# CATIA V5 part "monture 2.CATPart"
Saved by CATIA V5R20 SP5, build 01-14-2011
Part number: monture 2
Publications: "Face", "Face1", "Face2", "Face3"
Bounding box of the stored display mesh (mm): x -200 to 10, y -75 to 75, z -75 to 75
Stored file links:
  U:\IAO\Nouveau dossier\monture 2.CATPart
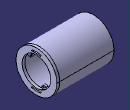
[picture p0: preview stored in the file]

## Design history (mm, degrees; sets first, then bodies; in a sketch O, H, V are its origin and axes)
Body1 (main body)
  Sketch1 on yz-plane, origin (0, 0, 0), H (0, 1, 0), V (0, 0, 1)
    circle A1 centre (0, 0) radius 75
    arc A2 centre (0, 0) radius 62.5 from (15.625, 60.5154) to (-15.625, 60.5154) ccw
    arc A3 centre (0, 0) radius 57.5 from (14.375, 55.6741) to (-14.375, 55.6741) ccw
    arc A4 centre (-15, 58.0948) radius 2.5 from (-15.625, 60.5154) to (-14.375, 55.6741) ccw
    point P1 (-15, 58.0948)
    arc A5 centre (15, 58.0948) radius 2.5 from (15.625, 60.5154) to (14.375, 55.6741) cw
    point P3 (15.625, 60.5154)
    point P4 (14.375, 55.6741)
    point P5 (-14.375, 55.6741)
    point P6 (-15.625, 60.5154)
    point P7 (-14.375, -55.6741)
    point P8 (-15.625, -60.5154)
    arc A6 centre (-15, -58.0948) radius 2.5 from (-15.625, -60.5154) to (-14.375, -55.6741) cw
    point P10 (14.375, -55.6741)
    point P11 (15.625, -60.5154)
    arc A7 centre (15, -58.0948) radius 2.5 from (15.625, -60.5154) to (14.375, -55.6741) ccw
    arc A8 centre (0, 0) radius 62.5 from (-15.625, -60.5154) to (15.625, -60.5154) ccw
    arc A9 centre (0, 0) radius 57.5 from (-14.375, -55.6741) to (14.375, -55.6741) ccw
    arc A10 centre (0, 0) radius 52.5 from (-38.2218, 35.9909) to (17.3744, -49.5417) ccw
    point P13 (-26, 40)
    construction line L1 through (0, -7.6191) direction (0, 1)
    construction line L2 through (0.6485, 0) direction (1, 0)
    arc A11 centre (-26, 40) radius 7.5 from (-32.0715, 35.597) to (-19.5113, 43.7612) ccw
    point P14 (0, 0)
    arc A12 centre (-16.0506, 45.7671) radius 4 from (-19.5113, 43.7612) to (-17.3744, 49.5417) cw
    arc A13 centre (-35.3097, 33.2487) radius 4 from (-32.0715, 35.597) to (-38.2218, 35.9909) ccw
    arc A14 centre (26, -40) radius 7.5 from (32.0715, -35.597) to (19.5113, -43.7612) ccw
    point P25 (26, -40)
    point P26 (33.4875, -40.4331)
    arc A15 centre (0, 0) radius 52.5 from (38.2218, -35.9909) to (-17.3744, 49.5417) ccw
    arc A16 centre (35.3097, -33.2487) radius 4 from (32.0715, -35.597) to (38.2218, -35.9909) ccw
    arc A17 centre (16.0506, -45.7671) radius 4 from (17.3744, -49.5417) to (19.5113, -43.7612) ccw
    radius A1 = 75
    radius A2 = 62.5
    radius A3 = 57.5
    distance P1 V = 15
    radius A10 = 52.5
    distance L1 P13 = 26
    distance P13 L2 = 40
    radius A11 = 7.5
    radius A12 = 4
    radius A13 = 4
    radius A14 = 7.5
    distance P25 L1 = 26
    distance H P25 = 40
    radius A16 = 4
    radius A17 = 4
    tangency: A4 A2, A4 A3, A12 A11, A12 A10, A13 A11, A13 A10, A16 A14, A16 A15, A17 A10, A17 A14
    symmetry: A4 A5 V, P5 P7 H, P6 P8 H, A4 A6 H, P4 P10 H, P3 P11 H, A5 A7 H
    coincidence: A2 A8, A3 A9, L2 H, L1 V, A10 P26, A10 A15, A14 P26, A15 P26
  Pad1: profile Sketch1, direction (1, 0, 0), length 10
  Sketch2 on start face of Pad1, origin (0, 0, 0), H (0, -1, 0), V (0, 0, 1)
    circle A1 centre (0, 0) radius 75
    reference projected circle E1 centre (0, 0) radius 75 from edge [start face of Pad1 | face of Pad1 from Sketch1.A1]
    reference projected circle E2 centre (0, 0) radius 75 from edge [start face of Pad1 | face of Pad1 from Sketch1.A1]
    circle A2 centre (0, 0) radius 70
    radius A2 = 70
    concentricity: E1 A1, A2 A1
    coincidence: E2 A1
  Pad2: profile Sketch2, direction (-1, 0, 0), length 200
  Sketch3 on end face of Pad1, origin (10, 0, 0), H (0, 1, 0), V (0, 0, 1)
    circle A1 centre (0, 0) radius 52.5
    reference projected arc E1 centre (0, 0) radius 52.5 from (38.2218, -35.9909) to (-17.3744, 49.5417) ccw from edge [end face of Pad1 | face of Pad1 from Sketch1.A15]
    coincidence: E1 A1
  Pocket1: profile Sketch3, direction (-1, 0, 0), length 2
  Sketch4 on end face of Pocket1, origin (8, 24.5422, -39.243), H (0, 1, 0), V (0, 0, 1)
    point P1 (0.2962, 1.4568)
    reference projected arc E1 centre (1.4578, -0.757) radius 7.5 from (7.5293, 3.646) to (-5.031, -4.5181) ccw from edge [face of Pad1 from Sketch1.A14 | end face of Pocket1]
    distance P1 E1 = 5
  Hole1: placed by Sketch4, at (8, 24.8384, -37.7863) direction (-1, 0, 0), diameter 5, through (limit type 3)
  Sketch5 on end face of Pocket1, origin (8, -24.2549, 37.3063), H (0, 1, 0), V (0, 0, 1)
    point P1 (-0.0845, 0.8249)
    reference projected arc E1 centre (-1.7451, 2.6937) radius 7.5 from (-7.8166, -1.7093) to (4.7436, 6.4549) ccw from edge [face of Pad1 from Sketch1.A11 | end face of Pocket1]
    distance P1 E1 = 5
  Hole2: placed by Sketch5, at (8, -24.3394, 38.1312) direction (-1, 0, 0), diameter 5, through (limit type 3)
